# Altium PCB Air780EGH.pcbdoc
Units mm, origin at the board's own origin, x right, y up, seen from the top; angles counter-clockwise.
Board outline 29.25 x 30.51 mm, 2 copper layers (Top Layer, Bottom Layer); 1 components, 0 nets, 109 pads, 0 vias.
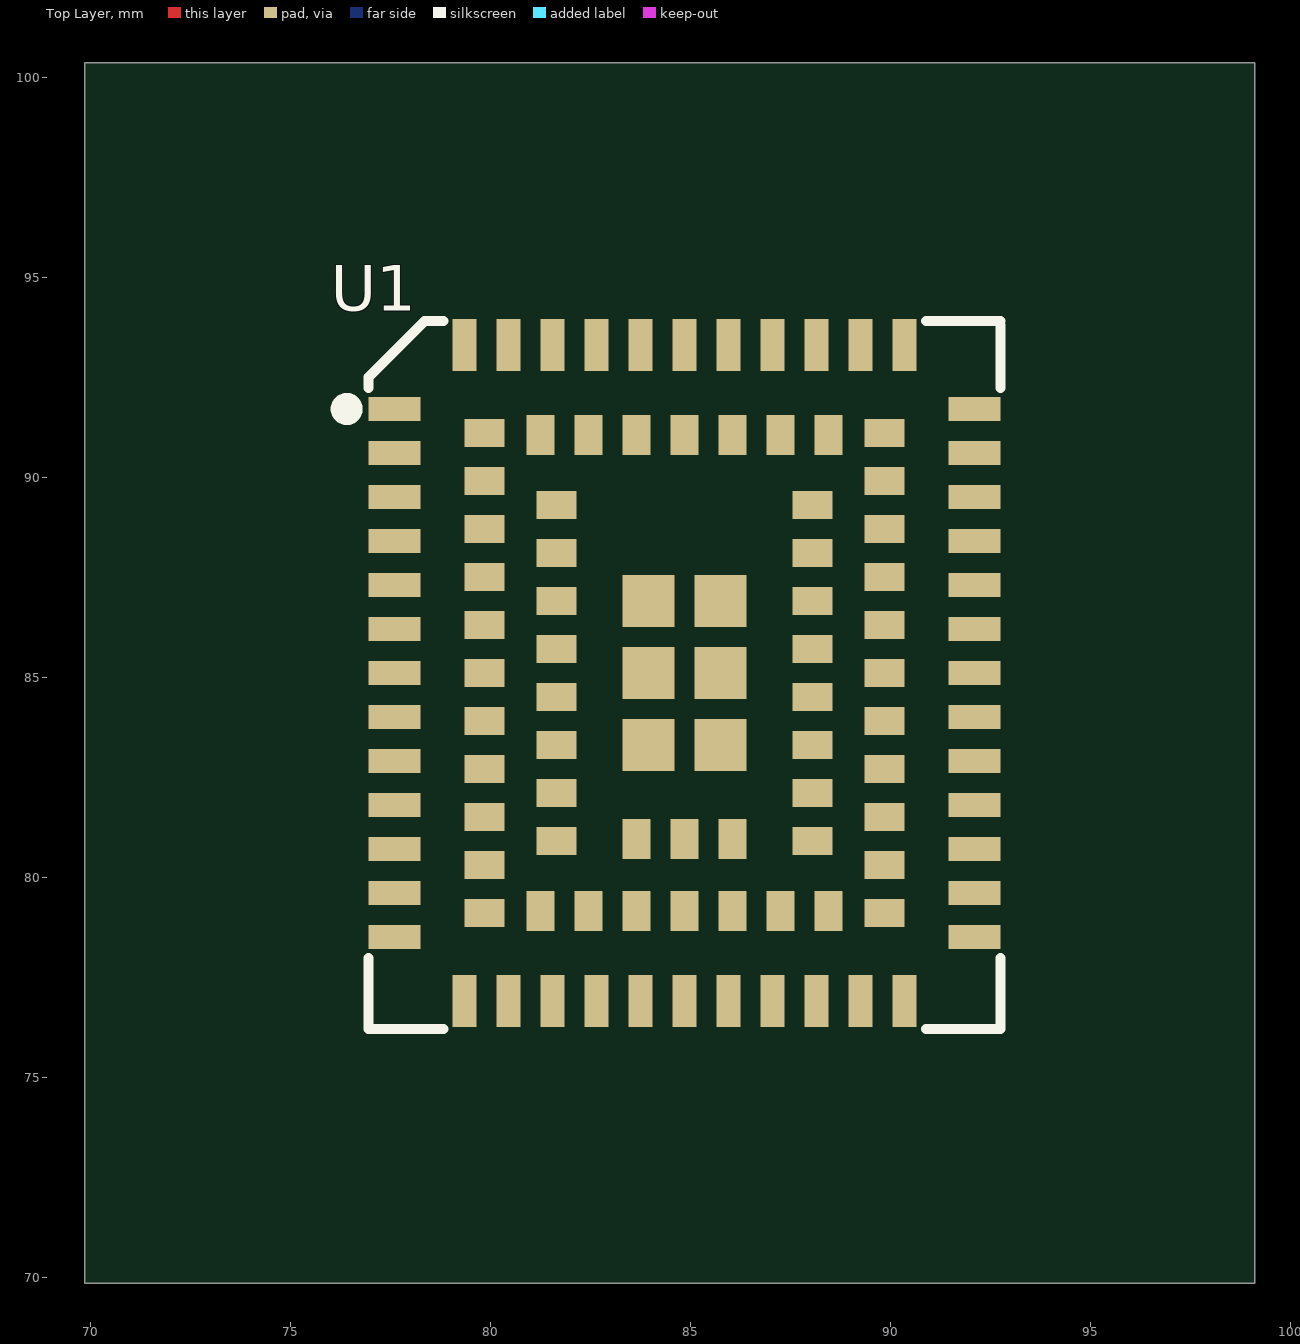
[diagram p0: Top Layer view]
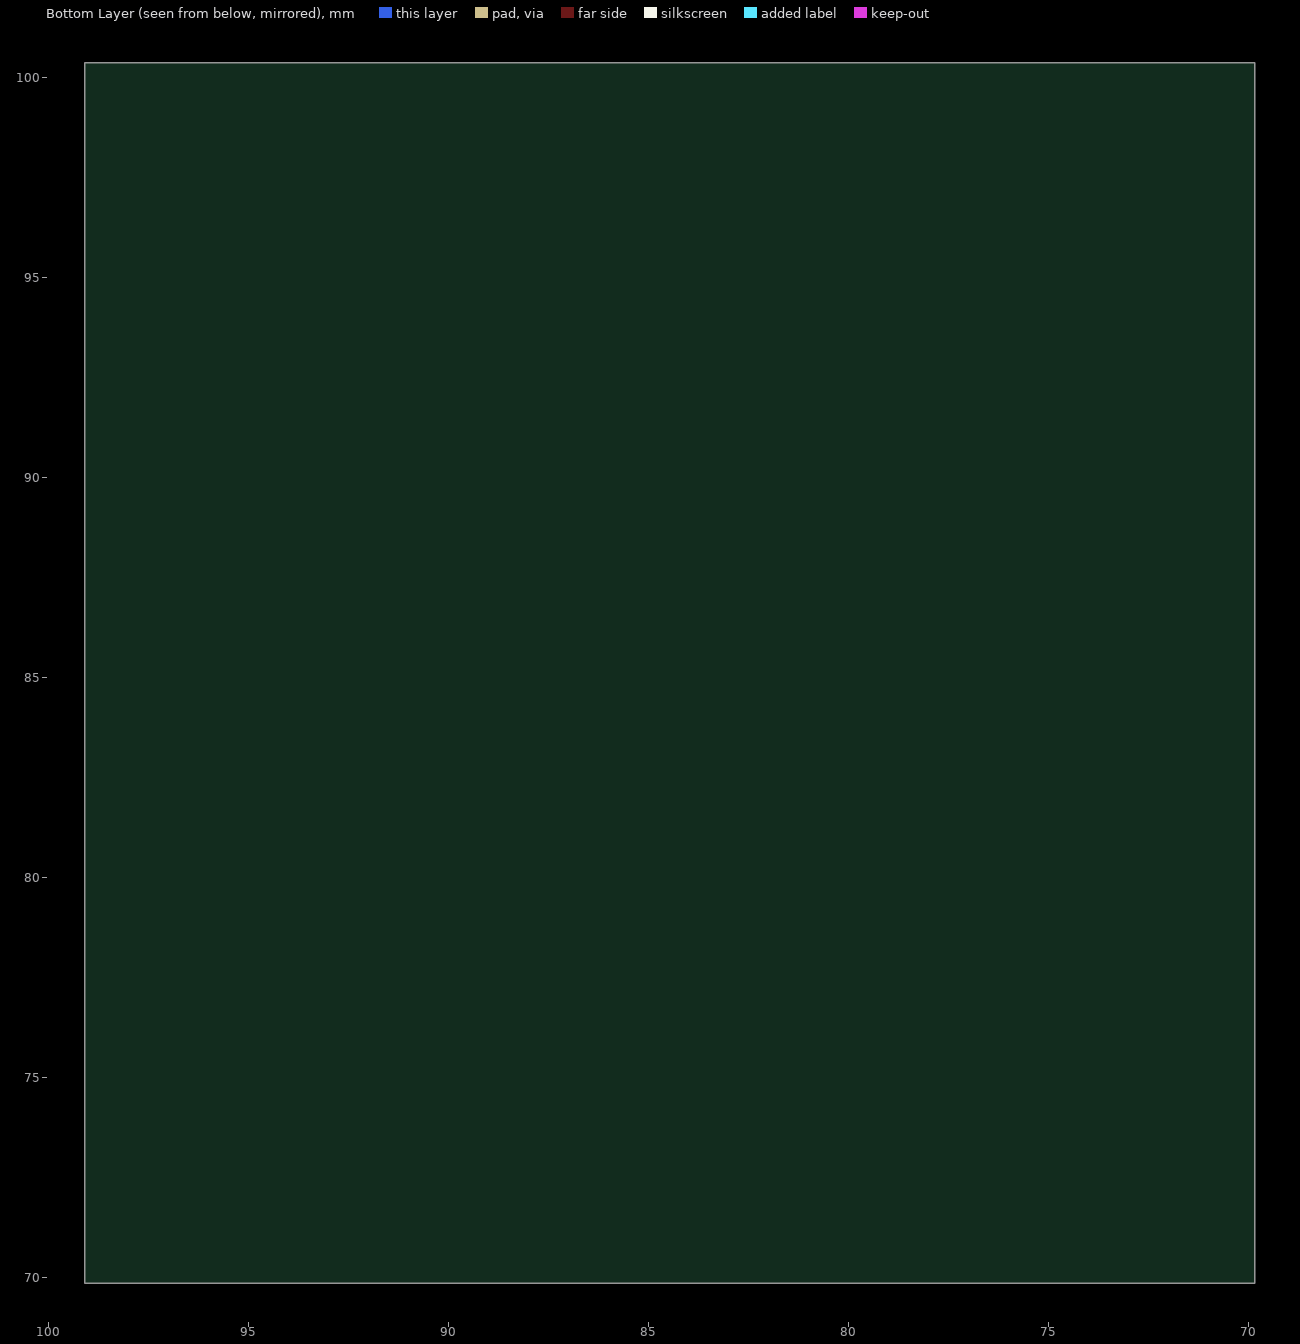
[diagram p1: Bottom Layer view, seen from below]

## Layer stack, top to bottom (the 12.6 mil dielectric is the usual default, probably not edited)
Top Layer: signal copper (thickness not stored)
Dielectric: dielectric 0.32, FR-4, Dk 4.8
Bottom Layer: signal copper (thickness not stored)

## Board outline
99.1,69.85 69.85,69.85 69.85,100.36 99.1,100.36

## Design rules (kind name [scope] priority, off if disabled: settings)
BoardOutlineClearance copperThickness1oz [All] p0: genericclearance=0.254 ignorepadtopadclearanceinfootprint=FALSE except(0: Arc-SplitContinuation Track-SplitContinuation SMDPad-SplitContinuation THPad-SplitContinuation Via-SplitContinuation Fill-SplitContinuation Poly-SplitContinuation Region-SplitContinuation Text-SplitContinuation; 0.152: Track-CutoutEdge SMDPad-CutoutEdge THPad-CutoutEdge Via-CutoutEdge Region-CutoutEdge; 0.3: Track-OutlineEdge SMDPad-OutlineEdge THPad-OutlineEdge Via-OutlineEdge Fill-OutlineEdge Region-OutlineEdge Poly-OutlineEdge Text-OutlineEdge Fill-CutoutEdge)
BoardOutlineClearance copperThickness2oz [All] p0: genericclearance=0.254 ignorepadtopadclearanceinfootprint=FALSE except(0: Arc-SplitContinuation Track-SplitContinuation SMDPad-SplitContinuation THPad-SplitContinuation Via-SplitContinuation Fill-SplitContinuation Poly-SplitContinuation Region-SplitContinuation Text-SplitContinuation; 0.152: Track-CutoutEdge SMDPad-CutoutEdge THPad-CutoutEdge Via-CutoutEdge Region-CutoutEdge; 0.3: Track-OutlineEdge SMDPad-OutlineEdge THPad-OutlineEdge Via-OutlineEdge Fill-OutlineEdge Region-OutlineEdge Poly-OutlineEdge Text-OutlineEdge Fill-CutoutEdge)
Clearance copperThickness1oz [All] p1: gap=0.178 ignorepadtopadclearanceinfootprint=FALSE except(0.102: Track-Track; 0.152: Track-SMDPad SMDPad-SMDPad Track-THPad SMDPad-THPad THPad-THPad Track-Via SMDPad-Via THPad-Via Via-Via SMDPad-Fill THPad-Fill Via-Fill Fill-Fill Track-Region SMDPad-Region THPad-Region Via-Region Region-Region Track-Poly SMDPad-Poly THPad-Poly Via-Poly Fill-Poly Region-Poly Poly-Poly Track-Text SMDPad-Text THPad-Text Via-Text Fill-Text Region-Text Poly-Text Text-Text; 0.175: Track-Hole SMDPad-Hole THPad-Hole Via-Hole Fill-Hole Region-Hole Poly-Hole Text-Hole Sheet-Hole; 0.3: Track-Fill Fill-Region Track-Sheet SMDPad-Sheet THPad-Sheet Via-Sheet Fill-Sheet Region-Sheet Poly-Sheet Text-Sheet)
Clearance copperThickness2oz [All] p1: gap=0.178 ignorepadtopadclearanceinfootprint=FALSE except(0.152: Track-SMDPad SMDPad-SMDPad Track-THPad SMDPad-THPad THPad-THPad Track-Via SMDPad-Via THPad-Via Via-Via SMDPad-Fill THPad-Fill Via-Fill Fill-Fill Track-Region SMDPad-Region THPad-Region Via-Region Region-Region Track-Poly SMDPad-Poly THPad-Poly Via-Poly Fill-Poly Region-Poly Poly-Poly Track-Text SMDPad-Text THPad-Text Via-Text Fill-Text Region-Text Poly-Text Text-Text; 0.175: Track-Hole SMDPad-Hole THPad-Hole Via-Hole Fill-Hole Region-Hole Poly-Hole Text-Hole Sheet-Hole; 0.203: Track-Track; 0.3: Track-Fill Fill-Region Track-Sheet SMDPad-Sheet THPad-Sheet Via-Sheet Fill-Sheet Region-Sheet Poly-Sheet Text-Sheet)
DiffPairsRouting differentialPair [All] p1: maxuncoupledlength=10 minlimit=6 maxlimit=6 mostfreqgap=6 toplayer_minwidth=5 toplayer_prefwidth=10 toplayer_maxwidth=100 bottomlayer_minwidth=5 bottomlayer_prefwidth=10 bottomlayer_maxwidth=100
PasteMaskExpansion pasteMaskExpansion [All] p1: expansion=0
PlaneConnect innerPlane [All] p1: planeconnectstyle=Relief reliefexpansion=0.508 reliefentries=4 reliefconductorwidth=0.254 reliefairgap=0.254
PolygonConnect copperRegion [All] p1: connectstyle=Relief reliefentries=4 reliefconductorwidth=10 polygonreliefangle="90 Angle" airgapwidth=10
RoutingVias viaSize [All] p1: viastyle="Through Hole" holewidth=12.0078 minholewidth=11.811 maxholewidth=248.0314 width=24.0158 minwidth=19.685 maxwidth=393.7008
SolderMaskExpansion solderMaskExpansion [All] p1: useseparateexpansions=TRUE expansion=2 expansionbottom=2
Width copperThickness1oz [All] p1: maxlimit=100 minlimit=5 preferedwidth=10
Width copperThickness2oz [All] p1: maxlimit=100 minlimit=8 preferedwidth=10

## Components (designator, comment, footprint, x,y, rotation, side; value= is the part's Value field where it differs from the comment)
U1 "AIR780EHM" LGA-109_L17.7-W15.8-AIR780E 84.85,85.1 r0 top

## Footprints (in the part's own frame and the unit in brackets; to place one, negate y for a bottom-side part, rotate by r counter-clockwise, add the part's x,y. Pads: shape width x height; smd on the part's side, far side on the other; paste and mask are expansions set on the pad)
LGA-109_L17.7-W15.8-AIR780E [mm]
  rect 1.3x0.6 smd: 1(-7.25,6.6) 2(-7.25,5.5) 3(-7.25,4.4) 4(-7.25,3.3) 5(-7.25,2.2) 6(-7.25,1.1) 7(-7.25,0) 8(-7.25,-1.1) 9(-7.25,-2.2) 10(-7.25,-3.3) 11(-7.25,-4.4) 12(-7.25,-5.5) 13(-7.25,-6.6) 23(7.25,-6.6) 24(7.25,-5.5) 25(7.25,-4.4) 26(7.25,-3.3) 27(7.25,-2.2) 28(7.25,-1.1) 29(7.25,0) 30(7.25,1.1) 31(7.25,2.2) 32(7.25,3.3) 33(7.25,4.4) 34(7.25,5.5) 35(7.25,6.6)
  rect 0.6x1.3 smd: 14(-4.4,-8.2) 15(-3.3,-8.2) 16(-2.2,-8.2) 17(-1.1,-8.2) 18(0,-8.2) 19(1.1,-8.2) 20(2.2,-8.2) 21(3.3,-8.2) 22(4.4,-8.2) 36(4.4,8.2) 37(3.3,8.2) 38(2.2,8.2) 39(1.1,8.2) 40(0,8.2) 41(-1.1,8.2) 42(-2.2,8.2) 43(-3.3,8.2) 44(-4.4,8.2) 95(-5.5,-8.2) 96(5.5,-8.2) 97(5.5,8.2) 98(-5.5,8.2)
  rect 1x0.7 smd: 45(-5,4.8) 46(-5,3.6) 47(-5,2.4) 48(-5,1.2) 49(-5,0) 50(-5,-1.2) 51(-5,-2.4) 52(-5,-3.6) 53(-5,-4.8) 59(5,-4.8) 60(5,-3.6) 61(5,-2.4) 62(5,-1.2) 63(5,0) 64(5,1.2) 65(5,2.4) 66(5,3.6) 67(5,4.8) 73(-3.2,4.2) 74(-3.2,3) 75(-3.2,1.8) 76(-3.2,0.6) 77(-3.2,-0.6) 78(-3.2,-1.8) 79(-3.2,-3) 80(-3.2,-4.2) 81(3.2,-4.2) 82(3.2,-3) 83(3.2,-1.8) 84(3.2,-0.6) 85(3.2,0.6) 86(3.2,1.8) 87(3.2,3) 88(3.2,4.2) 99(-5,6) 100(-5,-6) 103(5,-6) 104(5,6)
  rect 0.7x1 smd: 54(-2.4,-5.95) 55(-1.2,-5.95) 56(0,-5.95) 57(1.2,-5.95) 58(2.4,-5.95) 68(2.4,5.95) 69(1.2,5.95) 70(0,5.95) 71(-1.2,5.95) 72(-2.4,5.95) 101(-3.6,-5.95) 102(3.6,-5.95) 105(3.6,5.95) 106(-3.6,5.95) 107(-1.2,-4.15) 108(0,-4.15) 109(1.2,-4.15)
  rect 1.3x1.3 smd: 89(-0.9,1.8) 90(-0.9,0) 91(-0.9,-1.8) 92(0.9,-1.8) 93(0.9,0) 94(0.9,1.8)
  silkscreen extent -8.65,-8.9 7.9,8.8

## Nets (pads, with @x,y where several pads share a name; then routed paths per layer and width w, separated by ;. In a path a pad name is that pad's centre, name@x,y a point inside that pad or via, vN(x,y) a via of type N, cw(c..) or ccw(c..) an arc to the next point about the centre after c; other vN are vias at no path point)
pads on no net: U1.1 U1.2 U1.3 U1.4 U1.5 U1.6 U1.7 U1.8 U1.9 U1.10 U1.11 U1.12 U1.13 U1.14 U1.15 U1.16 U1.17 U1.18 U1.19 U1.20 U1.21 U1.22 U1.23 U1.24 U1.25 U1.26 U1.27 U1.28 U1.29 U1.30 U1.31 U1.32 U1.33 U1.34 U1.35 U1.36 U1.37 U1.38 U1.39 U1.40 U1.41 U1.42 U1.43 U1.44 U1.45 U1.46 U1.47 U1.48 U1.49 U1.50 U1.51 U1.52 U1.53 U1.54 U1.55 U1.56 U1.57 U1.58 U1.59 U1.60 U1.61 U1.62 U1.63 U1.64 U1.65 U1.66 U1.67 U1.68 U1.69 U1.70 U1.71 U1.72 U1.73 U1.74 U1.75 U1.76 U1.77 U1.78 U1.79 U1.80 U1.81 U1.82 U1.83 U1.84 U1.85 U1.86 U1.87 U1.88 U1.89 U1.90 U1.91 U1.92 U1.93 U1.94 U1.95 U1.96 U1.97 U1.98 U1.99 U1.100 U1.101 U1.102 U1.103 U1.104 U1.105 U1.106 U1.107 U1.108 U1.109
